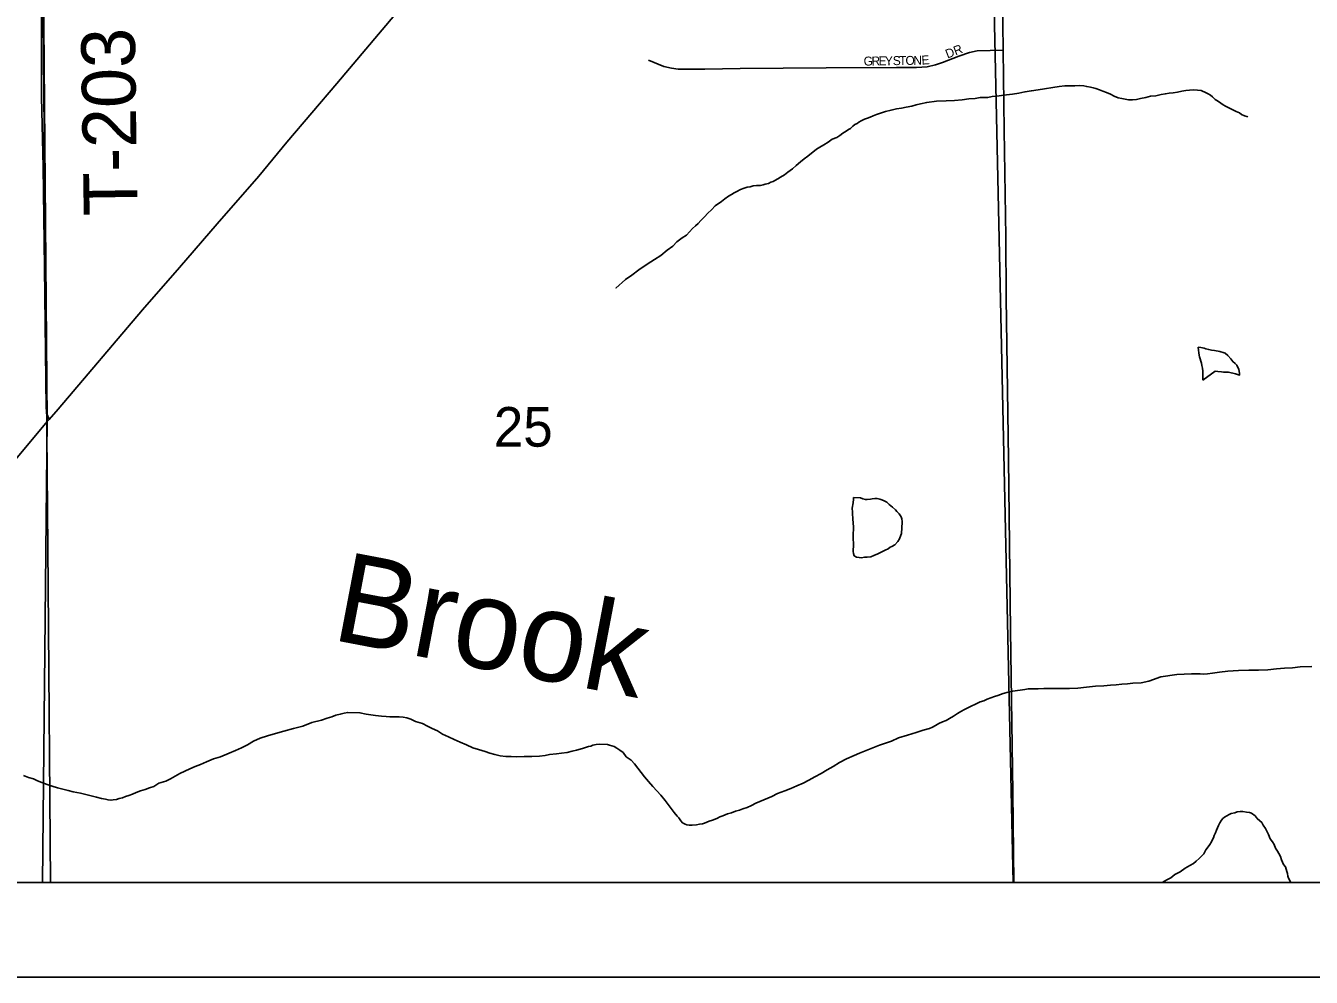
# Model space of a CAD drawing. Extents: x 10.6 to 44.6, y -2.6 to 23.4.
# Drawn here: x 15.273 to 16.631, y 15.426 to 16.432 of the extents above; entities that cross this region are included whole.
import ezdxf

# ---------------------------------------------------------------- set-up
doc = ezdxf.new("R2010")
doc.units = 0
for name, color, linetype in [('GM_X_County', 7, 'Continuous'), ('GM_X_County_Road', 7, 'Continuous'), ('GM_X_Minor_Lake', 7, 'Continuous'), ('GM_X_Minor_River', 7, 'Continuous'), ('GM_X_Minor_River_Text', 7, 'Continuous'), ('GM_X_Section', 7, 'Continuous'), ('GM_X_Section_Text', 7, 'Continuous'), ('GM_X_Township', 7, 'Continuous'), ('GM_X_Township_Road', 7, 'Continuous'), ('GM_X_Township_Road_Text', 7, 'Continuous'), ('GM_X_Township_Subdivision', 7, 'Continuous'), ('GM_X_Township_Subdivision_Text', 7, 'Continuous'), ('SH_Data', 7, 'Continuous')]:
    doc.layers.add(name, color=color, linetype=linetype)

msp = doc.modelspace()

# ---------------------------------------------------------------- linework, layer by layer
at = {"layer": 'GM_X_County'}
msp.add_lwpolyline([(20.0033, 15.5302), (20.0033, 22.3267), (13.2033, 22.3267), (13.2033, 15.5267), (19.8413, 15.5267)], dxfattribs=at)
at = {"layer": 'GM_X_County_Road'}
msp.add_lwpolyline([(16.2763, 18.1986), (16.2775, 18.1572), (16.2791, 18.0677), (16.2823, 17.8579), (16.286, 17.6424), (16.2902, 17.4286), (16.292, 17.333), (16.2926, 17.2804), (16.2943, 17.2251), (16.2954, 17.1849), (16.2974, 17.0561), (16.299, 16.9044), (16.301, 16.7657), (16.303, 16.5782), (16.3046, 16.4615), (16.3053, 16.4059), (16.3064, 16.3215), (16.308, 16.2088), (16.3086, 16.1439), (16.3111, 15.9738), (16.3131, 15.7931), (16.3156, 15.6219), (16.3166, 15.5267)], dxfattribs=at)
at = {"layer": 'GM_X_Minor_Lake'}
for points in [[(16.5342, 16.0876), (16.5287, 16.0887), (16.5256, 16.089), (16.5225, 16.0897), (16.5195, 16.0904), (16.5176, 16.0911), (16.5141, 16.0918), (16.5115, 16.0921), (16.5119, 16.0891), (16.512, 16.0861), (16.5124, 16.0838), (16.5128, 16.0819), (16.5149, 16.0755), (16.5153, 16.0728), (16.5158, 16.0702), (16.5162, 16.0667), (16.5163, 16.0622), (16.5164, 16.0572)], [(16.5164, 16.0572), (16.5295, 16.0667), (16.5322, 16.0664), (16.536, 16.0661), (16.5383, 16.0657), (16.541, 16.0658), (16.5433, 16.0658), (16.5509, 16.0641), (16.5551, 16.0627), (16.5551, 16.0646), (16.5542, 16.0688), (16.5522, 16.0733), (16.5503, 16.0748), (16.5479, 16.077), (16.546, 16.08), (16.5429, 16.0833), (16.5398, 16.0859), (16.5378, 16.0866), (16.5352, 16.0873), (16.5342, 16.0876)], [(16.1471, 15.9335), (16.1472, 15.9316), (16.1469, 15.9278), (16.1459, 15.9221), (16.146, 15.9179), (16.1465, 15.9096), (16.147, 15.9077), (16.147, 15.9054), (16.1471, 15.9031), (16.1471, 15.9012), (16.1472, 15.8989), (16.1469, 15.8962), (16.1469, 15.8932), (16.147, 15.8909), (16.147, 15.889), (16.1471, 15.8856), (16.1471, 15.8833), (16.1472, 15.881), (16.1469, 15.8791), (16.1469, 15.8765), (16.1474, 15.8742), (16.1478, 15.8719), (16.1505, 15.8704), (16.1532, 15.8701), (16.1558, 15.8698), (16.1589, 15.8703), (16.1615, 15.8703), (16.1657, 15.8708), (16.1687, 15.872), (16.1729, 15.874), (16.177, 15.876), (16.1808, 15.8776), (16.1838, 15.8792), (16.186, 15.8808), (16.1879, 15.8816), (16.1909, 15.8835), (16.1942, 15.887), (16.1957, 15.8897), (16.1971, 15.8936), (16.1979, 15.8955), (16.1988, 15.9074)], [(16.1988, 15.9074), (16.1987, 15.9081), (16.1983, 15.9107), (16.1975, 15.913), (16.1955, 15.916), (16.1931, 15.9186), (16.1916, 15.9205), (16.1885, 15.9231), (16.185, 15.926), (16.1826, 15.9283), (16.1796, 15.9297), (16.1773, 15.9308), (16.175, 15.9315), (16.1723, 15.9322), (16.1696, 15.9325), (16.167, 15.9321), (16.1651, 15.9317), (16.1617, 15.9312), (16.1598, 15.9312), (16.1571, 15.9319), (16.1548, 15.933), (16.1471, 15.9335)]]:
    msp.add_lwpolyline(points, dxfattribs=at)
at = {"layer": 'GM_X_Minor_River'}
for points in [[(15.8963, 16.1546), (15.9064, 16.1636), (15.8963, 16.1546), (15.9064, 16.1636), (15.9131, 16.1683), (15.9206, 16.1738), (15.9292, 16.1801), (15.9371, 16.1848), (15.9438, 16.1892), (15.9505, 16.1947), (15.9565, 16.199), (15.9606, 16.2036), (15.9662, 16.2076), (15.9707, 16.2107), (15.9741, 16.2142), (15.977, 16.2177), (15.9804, 16.2205), (15.983, 16.2228), (15.986, 16.2259), (15.9897, 16.2298), (15.9934, 16.2337), (15.9971, 16.2372), (16.0012, 16.2415), (16.0076, 16.2462), (16.0113, 16.2489), (16.0151, 16.2517), (16.0184, 16.2537), (16.0211, 16.2552), (16.0241, 16.2568), (16.0278, 16.2588), (16.0316, 16.2601), (16.035, 16.2613), (16.038, 16.2617), (16.0411, 16.2626), (16.0449, 16.263), (16.049, 16.2631), (16.0517, 16.2636), (16.054, 16.2644), (16.0574, 16.2652), (16.06, 16.2664), (16.0623, 16.2672), (16.0641, 16.2684), (16.0672, 16.27), (16.0702, 16.272), (16.0743, 16.2743), (16.078, 16.2771), (16.0829, 16.2806), (16.0866, 16.2841), (16.0911, 16.288), (16.0952, 16.2912), (16.0989, 16.2939), (16.1083, 16.3014), (16.1117, 16.3037), (16.1158, 16.3061), (16.1203, 16.3089), (16.1248, 16.312), (16.1297, 16.3137), (16.1327, 16.316), (16.1361, 16.3184), (16.1394, 16.3204), (16.1421, 16.3223), (16.1439, 16.3231), (16.1465, 16.3258), (16.1488, 16.3274), (16.151, 16.3286), (16.1529, 16.3298), (16.1555, 16.3314), (16.1589, 16.333), (16.1619, 16.3342), (16.165, 16.3354), (16.168, 16.3366), (16.1714, 16.3382), (16.1759, 16.3394), (16.1812, 16.3411), (16.1869, 16.3427), (16.1925, 16.344), (16.1979, 16.3449), (16.2028, 16.3458), (16.2088, 16.347), (16.2134, 16.3483), (16.2179, 16.3492), (16.2247, 16.3508), (16.235, 16.3522), (16.2452, 16.3524), (16.254, 16.353), (16.262, 16.3536), (16.2692, 16.3545), (16.2756, 16.355), (16.2809, 16.3559), (16.2855, 16.356), (16.2893, 16.3561), (16.2938, 16.357), (16.2988, 16.3575), (16.3037, 16.358), (16.309, 16.3588), (16.3151, 16.3597), (16.3219, 16.3607), (16.3284, 16.3619), (16.3352, 16.3632), (16.3424, 16.3642), (16.3644, 16.3677)], [(16.3644, 16.3677), (16.3704, 16.3682), (16.3761, 16.3684), (16.3811, 16.3685), (16.3864, 16.3686), (16.3906, 16.3683), (16.3937, 16.3676), (16.3975, 16.3669), (16.4005, 16.3663), (16.4032, 16.3655), (16.4071, 16.3641), (16.4105, 16.3627), (16.4147, 16.3612), (16.4186, 16.3594), (16.4228, 16.3576), (16.4267, 16.3558), (16.4309, 16.3548), (16.4343, 16.3541), (16.4378, 16.3534), (16.4419, 16.3535), (16.4461, 16.354), (16.4503, 16.3548), (16.456, 16.3561), (16.4609, 16.3573), (16.4666, 16.3579), (16.4722, 16.3591), (16.4768, 16.36), (16.4806, 16.3605), (16.4848, 16.3609), (16.4897, 16.3618), (16.4942, 16.3627), (16.4984, 16.3635), (16.5022, 16.3636), (16.5068, 16.3641), (16.5106, 16.3638), (16.5144, 16.3635), (16.5198, 16.361), (16.5221, 16.3599), (16.5244, 16.3584), (16.5267, 16.3566), (16.5294, 16.354), (16.5329, 16.3518), (16.5352, 16.3499), (16.5379, 16.3484), (16.5403, 16.347), (16.5422, 16.3459), (16.5514, 16.3411), (16.5549, 16.3397), (16.5572, 16.3382), (16.5603, 16.3368), (16.5629, 16.3361), (16.5637, 16.3357)], [(16.2375, 15.6947), (16.2412, 15.6963), (16.245, 15.6979), (16.2487, 15.6999), (16.2529, 15.7023), (16.257, 15.7051), (16.2608, 15.7074), (16.2645, 15.7094), (16.2694, 15.7118), (16.2724, 15.7134), (16.2754, 15.7146), (16.2777, 15.7158), (16.2811, 15.7174), (16.2848, 15.7186), (16.2886, 15.7202), (16.2924, 15.7219), (16.2962, 15.7231), (16.2996, 15.7243), (16.3026, 15.7251), (16.3052, 15.7263), (16.3105, 15.7276), (16.3154, 15.7289), (16.3283, 15.7307), (16.3317, 15.7311), (16.3336, 15.7312), (16.3355, 15.7312), (16.3382, 15.7313), (16.3424, 15.7314), (16.3485, 15.7315), (16.358, 15.7317), (16.3664, 15.7315), (16.3755, 15.7317), (16.3842, 15.7319), (16.3933, 15.7329), (16.4028, 15.7339), (16.4116, 15.7345), (16.4188, 15.735), (16.4249, 15.7355), (16.4309, 15.736), (16.4366, 15.7366), (16.4423, 15.7371), (16.4511, 15.7376), (16.4594, 15.7394), (16.4719, 15.7438), (16.4889, 15.7465), (16.5045, 15.7472), (16.5136, 15.7471), (16.5171, 15.7468), (16.5212, 15.7472), (16.5266, 15.7477), (16.5338, 15.7487), (16.5429, 15.75), (16.5539, 15.7506), (16.5649, 15.7509), (16.5752, 15.7511), (16.5851, 15.7513), (16.5942, 15.7523), (16.6025, 15.7529), (16.6109, 15.7535), (16.6192, 15.7544), (16.6314, 15.7547)], [(15.2704, 15.6395), (15.2757, 15.6374), (15.2807, 15.636), (15.285, 15.6342), (15.2896, 15.6324), (15.2953, 15.6302), (15.3007, 15.6284), (15.3064, 15.6267), (15.3118, 15.6253), (15.3175, 15.6239), (15.3229, 15.6225), (15.3305, 15.6211), (15.3474, 15.6166), (15.3527, 15.6152), (15.3569, 15.6145), (15.3596, 15.6138), (15.3627, 15.6135), (15.3649, 15.6139), (15.3684, 15.6144), (15.3714, 15.6152), (15.3748, 15.616), (15.3782, 15.6173), (15.3816, 15.6185), (15.3853, 15.6201), (15.3895, 15.6217), (15.394, 15.6233), (15.3989, 15.625), (15.4035, 15.6266), (15.408, 15.6282), (15.4132, 15.6314), (15.4208, 15.6338), (15.4257, 15.6362), (15.4306, 15.639), (15.4355, 15.6418), (15.4407, 15.6442), (15.446, 15.6466), (15.4516, 15.649), (15.4573, 15.6514), (15.4637, 15.6542), (15.4709, 15.6571), (15.4784, 15.6595), (15.4875, 15.6631), (15.4943, 15.666), (15.5007, 15.6688), (15.5071, 15.672), (15.5134, 15.6759), (15.5202, 15.6791), (15.5281, 15.6816), (15.5365, 15.6841), (15.5455, 15.6865), (15.5554, 15.6894), (15.5656, 15.6919), (15.575, 15.6956), (15.5852, 15.6981), (15.5913, 15.7001), (15.5962, 15.7018), (15.6003, 15.7034), (15.6049, 15.7043), (15.609, 15.7055), (15.6128, 15.7063), (15.6258, 15.7059), (15.6323, 15.7045), (15.6422, 15.7032), (15.6487, 15.7022), (15.6536, 15.702), (15.6574, 15.7017), (15.6601, 15.7017), (15.6624, 15.7018), (15.6647, 15.7018), (15.6673, 15.7015), (15.6715, 15.7012), (15.6753, 15.7005), (15.6796, 15.6991), (15.6846, 15.6966), (15.6918, 15.6945), (15.6972, 15.6919), (15.7022, 15.6894), (15.7076, 15.6868), (15.713, 15.6835), (15.7192, 15.6806), (15.7253, 15.6777), (15.7315, 15.6748), (15.7384, 15.6719), (15.7449, 15.669), (15.7511, 15.6673), (15.758, 15.6651)], [(15.758, 15.6651), (15.7629, 15.6634), (15.7683, 15.662), (15.774, 15.6606), (15.7798, 15.6599), (15.7855, 15.6597), (15.7916, 15.6594), (15.7992, 15.6596), (15.8075, 15.6598), (15.8155, 15.66), (15.8216, 15.6609), (15.8261, 15.6618), (15.8333, 15.6627), (15.8387, 15.6632), (15.8447, 15.6641), (15.85, 15.6653), (15.8546, 15.6666), (15.8583, 15.6674), (15.8621, 15.6687), (15.8651, 15.6695), (15.8674, 15.6703), (15.8697, 15.6707), (15.872, 15.6716), (15.8754, 15.6724), (15.8784, 15.6728), (15.8872, 15.6723), (15.8895, 15.6716), (15.8918, 15.6709), (15.8944, 15.6702), (15.8971, 15.6687), (15.9002, 15.6665), (15.9037, 15.6639), (15.9072, 15.6594), (15.9123, 15.6557), (15.9158, 15.652), (15.9193, 15.6475), (15.9228, 15.643), (15.9264, 15.6382), (15.9307, 15.6333), (15.9353, 15.6281), (15.9396, 15.6236), (15.9435, 15.6188), (15.9482, 15.6132), (15.9526, 15.6076), (15.9577, 15.6005), (15.9608, 15.5967), (15.9627, 15.5949), (15.9647, 15.5919), (15.9667, 15.5896), (15.9694, 15.5882), (15.9713, 15.5874), (15.9736, 15.5871), (15.9766, 15.5872), (15.9812, 15.5877), (15.9846, 15.5881), (15.9876, 15.5886), (15.9899, 15.5894), (15.9921, 15.5902), (15.9948, 15.5914), (15.9982, 15.5926), (16.0012, 15.5935), (16.0035, 15.5946), (16.0061, 15.5959), (16.0091, 15.5971), (16.014, 15.5991), (16.0182, 15.6003), (16.0227, 15.6019), (16.0269, 15.6032), (16.0302, 15.6044), (16.0348, 15.606), (16.0393, 15.608), (16.0442, 15.6104), (16.0608, 15.6176), (16.0668, 15.6208), (16.0747, 15.6233), (16.0811, 15.6261), (16.0875, 15.6289), (16.0939, 15.6317), (16.0999, 15.6349), (16.1063, 15.6381), (16.1131, 15.6417), (16.1195, 15.6456), (16.1259, 15.6492), (16.1326, 15.6535), (16.1398, 15.6571), (16.1481, 15.6607), (16.1537, 15.6631), (16.159, 15.6655), (16.1643, 15.6676), (16.1695, 15.6696), (16.1748, 15.6716), (16.1809, 15.6737), (16.1873, 15.6761), (16.1948, 15.6793), (16.2043, 15.6822), (16.2133, 15.685), (16.2209, 15.6875), (16.2277, 15.6892), (16.2307, 15.6908), (16.2337, 15.6924), (16.2375, 15.6947)], [(16.4732, 15.5267), (16.4783, 15.5294), (16.4824, 15.5317), (16.4869, 15.5349), (16.4922, 15.538), (16.4978, 15.5416), (16.5027, 15.5444), (16.5064, 15.5467), (16.5094, 15.5491), (16.5124, 15.5518), (16.515, 15.5545), (16.5172, 15.5569), (16.5194, 15.5611), (16.522, 15.5642), (16.5238, 15.5669), (16.5253, 15.5696), (16.5264, 15.5719), (16.5275, 15.5739), (16.5282, 15.5762), (16.5296, 15.5792), (16.5307, 15.5819), (16.5318, 15.5842), (16.5329, 15.5869), (16.5344, 15.5896), (16.5362, 15.5923), (16.5373, 15.5942), (16.5392, 15.5958), (16.544, 15.5986), (16.5463, 15.5994), (16.5501, 15.6002), (16.5527, 15.6011), (16.5558, 15.6015), (16.5584, 15.6016), (16.5626, 15.6009), (16.5657, 15.6006), (16.5676, 15.5999), (16.5715, 15.5969), (16.5738, 15.5943), (16.5765, 15.5917), (16.5785, 15.5899), (16.5801, 15.5872), (16.5824, 15.5835), (16.584, 15.5808), (16.5856, 15.5775), (16.5876, 15.5729), (16.59, 15.5696), (16.5916, 15.5666), (16.5932, 15.5628), (16.5952, 15.5598), (16.5967, 15.5572), (16.5983, 15.5542), (16.5996, 15.5504), (16.6016, 15.5455), (16.6035, 15.5432), (16.6043, 15.5406), (16.6052, 15.5383), (16.6056, 15.5361), (16.606, 15.5334), (16.6068, 15.5311), (16.6088, 15.5274), (16.6093, 15.5267)]]:
    msp.add_lwpolyline(points, dxfattribs=at)
at = {"layer": 'GM_X_Section'}
for p, q in [((15.2987, 15.5267), (16.3159, 15.5267)), ((16.3159, 15.5267), (17.2881, 15.5267))]:
    msp.add_line(p, q, dxfattribs=at)
for points in [[(17.2881, 15.5267), (17.2647, 16.6007), (16.2932, 16.5791), (16.3159, 15.5267)], [(16.3159, 15.5267), (16.2932, 16.5791), (15.2902, 16.5559), (15.2932, 16.204), (15.2963, 15.8392), (15.2987, 15.5267)]]:
    msp.add_lwpolyline(points, dxfattribs=at)
at = {"layer": 'GM_X_Township'}
msp.add_line((15.2903, 15.5267), (19.8413, 15.5267), dxfattribs=at)
for points in [[(13.2033, 20.8217), (13.2033, 15.5267), (15.2903, 15.5267)], [(15.2903, 15.5267), (15.2954, 16.015), (15.2788, 17.979), (15.2737, 18.9996)], [(15.2737, 18.9996), (15.2788, 17.979), (15.2954, 16.015), (15.2903, 15.5267)]]:
    msp.add_lwpolyline(points, dxfattribs=at)
at = {"layer": 'GM_X_Township_Road'}
for points in [[(15.2973, 16.0158), (15.2953, 16.0211), (15.2943, 16.0277), (15.2926, 16.1765), (15.291, 16.2829), (15.2894, 16.3563), (15.2892, 16.4328), (15.2883, 16.5432), (15.2854, 16.7208), (15.2851, 16.7668), (15.2845, 16.905), (15.2837, 17.2802)], [(15.7105, 16.5004), (15.6319, 16.4072), (15.6012, 16.3708), (15.5486, 16.3088), (15.5188, 16.2728), (15.4748, 16.2227), (15.4351, 16.1763), (15.3962, 16.1316), (15.3069, 16.0268), (15.2973, 16.0158)], [(15.2973, 16.0158), (15.2954, 16.0136), (15.2638, 15.976), (15.2082, 15.9112), (15.1857, 15.8854), (15.1368, 15.8297), (15.0914, 15.7734), (15.0636, 15.7386), (15.0576, 15.7303), (15.0524, 15.7206), (15.0492, 15.713), (15.0463, 15.7024), (15.0443, 15.6899), (15.0409, 15.6519), (15.0344, 15.5314), (15.0343, 15.5267)]]:
    msp.add_lwpolyline(points, dxfattribs=at)
at = {"layer": 'GM_X_Township_Subdivision'}
msp.add_lwpolyline([(16.3053, 16.4059), (16.2779, 16.4052), (16.2698, 16.4036), (16.2584, 16.3998), (16.2413, 16.3931), (16.2339, 16.3906), (16.2249, 16.3886), (16.2137, 16.3877), (16.1928, 16.3877), (16.1182, 16.3874), (16.0274, 16.3867), (15.9901, 16.3861), (15.971, 16.3858), (15.962, 16.3861), (15.9551, 16.3869), (15.9467, 16.3887), (15.9305, 16.3956)], dxfattribs=at)
at = {"layer": 'SH_Data'}
msp.add_line((13.1028, 15.4265), (20.1028, 15.4265), dxfattribs=at)

# ---------------------------------------------------------------- texts
at = {"layer": 'GM_X_Minor_River_Text'}
msp.add_text('Brook', height=0.09475, rotation=349.2053, dxfattribs=at).set_placement((15.5943, 15.7834))
at = {"layer": 'GM_X_Section_Text'}
msp.add_text('25', height=0.04186, rotation=0, dxfattribs=at).set_placement((15.7672, 15.9871))
at = {"layer": 'GM_X_Township_Road_Text'}
msp.add_text('T-203', height=0.05682, rotation=90.846, dxfattribs=at).set_placement((15.3908, 16.2314))
at = {"layer": 'GM_X_Township_Subdivision_Text'}
for s, rotation, p in [('DR', 21.2552, (16.2465, 16.3971)), ('G', 0.9181, (16.158, 16.3897)), ('R', 0.9558, (16.1663, 16.3898)), ('E', 0.9289, (16.1738, 16.3899)), ('Y', 0.9279, (16.1805, 16.39)), ('S', 0.9364, (16.1888, 16.3902)), ('T', 0.9289, (16.1955, 16.3903)), ('O', 0.9279, (16.2022, 16.3904)), ('N', 0.9504, (16.2105, 16.3905)), ('E', 4.2185, (16.2194, 16.3907))]:
    msp.add_text(s, height=0.00947, rotation=rotation, dxfattribs=at).set_placement(p)

doc.saveas('drawing.dxf')
